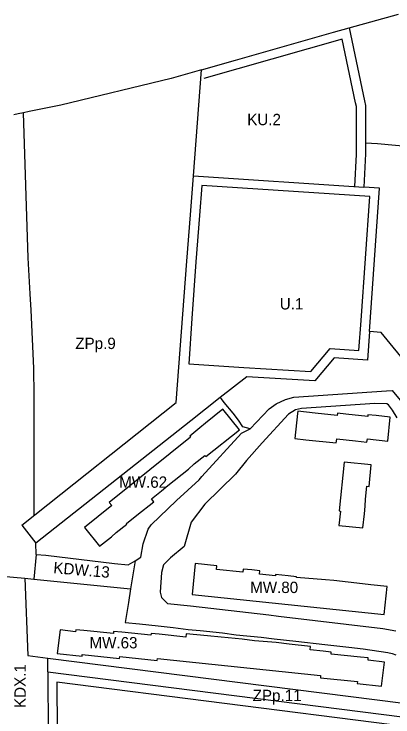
# Model space of a CAD drawing. Extents: x 7424434 to 7425898, y 5541432 to 5542659.
# Drawn here: x 7425417.1 to 7425584.1, y 5542027 to 5542336.8 of the extents above; entities that cross this region are included whole.
import ezdxf

# ---------------------------------------------------------------- set-up
doc = ezdxf.new("R2010")
doc.units = 0
for name, color, linetype in [('linie rozgraniczające', 7, 'Continuous'), ('nieprzekraczalne linie zabudowy', 7, 'Continuous'), ('obowiazujace linie zabudowy', 7, 'Continuous'), ('przeznaczenia terenów', 7, 'Continuous')]:
    doc.layers.add(name, color=color, linetype=linetype)

msp = doc.modelspace()

# ---------------------------------------------------------------- linework, layer by layer
at = {"layer": 'linie rozgraniczające'}
for p, q in [((7425564.85, 5542330.75), (7425586.62, 5542336.78)), ((7425558, 5542328.77), (7425564.85, 5542330.75)), ((7425564.85, 5542330.75), (7425571.55, 5542298.49)), ((7425514.68, 5542316.5), (7425558, 5542328.77)), ((7425499.7, 5542312.23), (7425514.68, 5542316.5)), ((7425499.7, 5542312.23), (7425486.38, 5542308.44)), ((7425496.15, 5542265.55), (7425499.7, 5542312.23)), ((7425486.38, 5542308.44), (7425437.7, 5542296.62)), ((7425437.7, 5542296.62), (7425423.76, 5542293.81)), ((7425571.55, 5542298.49), (7425572.02, 5542296.52)), ((7425423.76, 5542293.81), (7425421.28, 5542293.31)), ((7425572.02, 5542296.52), (7425572.05, 5542280.04)), ((7425418.88, 5542292.83), (7425416.94, 5542292.44)), ((7425421.28, 5542293.31), (7425418.88, 5542292.83)), ((7425423.39, 5542229.29), (7425421.28, 5542293.31)), ((7425572.05, 5542280.04), (7425577.28, 5542279.74)), ((7425572.05, 5542280.04), (7425572.08, 5542275.17)), ((7425577.28, 5542279.74), (7425593.66, 5542278.16)), ((7425572.08, 5542275.17), (7425571.31, 5542260.5)), ((7425494.84, 5542248.31), (7425496.15, 5542265.55)), ((7425496.15, 5542265.55), (7425571.31, 5542260.5)), ((7425578.15, 5542260.04), (7425571.31, 5542260.5)), ((7425573.76, 5542196.85), (7425578.15, 5542260.04)), ((7425493.28, 5542227.87), (7425494.84, 5542248.31)), ((7425424.22, 5542213.47), (7425423.39, 5542229.29)), ((7425488.55, 5542165.65), (7425493.28, 5542227.87)), ((7425424.6, 5542206.27), (7425424.22, 5542213.47)), ((7425425.89, 5542180.72), (7425424.6, 5542206.27)), ((7425573.76, 5542196.85), (7425572.88, 5542184.19)), ((7425578.96, 5542196.49), (7425573.76, 5542196.85)), ((7425613.28, 5542154.25), (7425578.96, 5542196.49)), ((7425558.18, 5542185.23), (7425549.74, 5542175.09)), ((7425572.88, 5542184.19), (7425558.18, 5542185.23)), ((7425425.97, 5542168.7), (7425425.89, 5542180.72)), ((7425519.67, 5542176.97), (7425508, 5542167.76)), ((7425549.74, 5542175.09), (7425519.67, 5542176.97)), ((7425540.42, 5542167.89), (7425581.26, 5542170.76)), ((7425581.26, 5542170.76), (7425583.73, 5542170.93)), ((7425583.73, 5542170.93), (7425600.13, 5542150.9)), ((7425425.97, 5542154.26), (7425425.97, 5542168.7)), ((7425508, 5542167.76), (7425494.99, 5542157.49)), ((7425508.36, 5542167.31), (7425508, 5542167.76)), ((7425509.4, 5542166.07), (7425508.36, 5542167.31)), ((7425532.64, 5542164.96), (7425536.8, 5542166.94)), ((7425536.8, 5542166.94), (7425540.42, 5542167.89)), ((7425420.52, 5542111.53), (7425488.55, 5542165.65)), ((7425509.69, 5542165.65), (7425509.4, 5542166.07)), ((7425513.64, 5542160.82), (7425509.69, 5542165.65)), ((7425529.54, 5542162.73), (7425532.64, 5542164.96)), ((7425576.13, 5542165.08), (7425543.76, 5542163)), ((7425581.46, 5542165.01), (7425576.13, 5542165.08)), ((7425582.21, 5542164.58), (7425581.46, 5542165.01)), ((7425583.91, 5542162.26), (7425582.21, 5542164.58)), ((7425516.08, 5542157.75), (7425513.64, 5542160.82)), ((7425521.15, 5542154), (7425529.54, 5542162.73)), ((7425538.14, 5542160.42), (7425526.47, 5542147.77)), ((7425541.12, 5542162.29), (7425538.14, 5542160.42)), ((7425543.76, 5542163), (7425541.12, 5542162.29)), ((7425586, 5542158.81), (7425583.91, 5542162.26)), ((7425494.99, 5542157.49), (7425426.75, 5542103.63)), ((7425518, 5542154.84), (7425516.08, 5542157.75)), ((7425425.95, 5542115.85), (7425425.97, 5542154.26)), ((7425521.15, 5542154), (7425518, 5542154.84)), ((7425499.92, 5542133.01), (7425517.38, 5542152.01)), ((7425517.38, 5542152.01), (7425521.15, 5542154)), ((7425526.47, 5542147.77), (7425519.51, 5542139.99)), ((7425519.51, 5542139.99), (7425514.77, 5542133.95)), ((7425498.72, 5542131.46), (7425499.92, 5542133.01)), ((7425514.77, 5542133.95), (7425501.25, 5542120.85)), ((7425488.73, 5542122.34), (7425498.72, 5542131.46)), ((7425477.48, 5542111.71), (7425488.73, 5542122.34)), ((7425501.25, 5542120.85), (7425495.17, 5542112.88)), ((7425420.52, 5542111.53), (7425426.75, 5542103.63)), ((7425476.27, 5542109.7), (7425477.48, 5542111.71)), ((7425495.17, 5542112.88), (7425492.04, 5542102.11)), ((7425474.09, 5542103.26), (7425476.27, 5542109.7)), ((7425426.91, 5542098.62), (7425426.75, 5542103.63)), ((7425472.94, 5542097.47), (7425474.09, 5542103.26)), ((7425492.04, 5542102.11), (7425486.11, 5542097.16)), ((7425426.91, 5542098.62), (7425431.09, 5542098.23)), ((7425431.09, 5542098.23), (7425461.44, 5542094.66)), ((7425467.35, 5542094.11), (7425470.54, 5542095.79)), ((7425470.54, 5542095.79), (7425468.51, 5542083.52)), ((7425470.54, 5542095.79), (7425472.94, 5542097.47)), ((7425486.11, 5542097.16), (7425482.92, 5542094.08)), ((7425461.44, 5542094.66), (7425467.35, 5542094.11)), ((7425482.92, 5542094.08), (7425482.12, 5542090.67)), ((7425411.87, 5542089.11), (7425421.8, 5542088.13)), ((7425482.12, 5542090.67), (7425481.47, 5542081.93)), ((7425421.8, 5542088.13), (7425423.13, 5542054.1)), ((7425421.8, 5542088.13), (7425425.88, 5542087.73)), ((7425425.88, 5542087.73), (7425468.51, 5542083.52)), ((7425468.51, 5542083.52), (7425467.51, 5542077.46)), ((7425481.47, 5542081.93), (7425482.16, 5542079.65)), ((7425467.51, 5542077.46), (7425466.06, 5542068.69)), ((7425482.16, 5542079.65), (7425484.82, 5542077.05)), ((7425484.82, 5542077.05), (7425494.84, 5542075.98)), ((7425494.84, 5542075.98), (7425529.41, 5542072.03)), ((7425529.41, 5542072.03), (7425533.72, 5542071.41)), ((7425533.72, 5542071.41), (7425579.75, 5542065.95)), ((7425466.06, 5542068.69), (7425472.4, 5542068.03)), ((7425472.4, 5542068.03), (7425480.57, 5542067.16)), ((7425480.57, 5542067.16), (7425487.18, 5542066.37)), ((7425487.18, 5542066.37), (7425493.91, 5542065.55)), ((7425493.91, 5542065.55), (7425499.19, 5542065.15)), ((7425499.19, 5542065.15), (7425509.05, 5542064.13)), ((7425579.75, 5542065.95), (7425585.36, 5542064.96)), ((7425509.05, 5542064.13), (7425514.98, 5542063.26)), ((7425514.98, 5542063.26), (7425526.1, 5542062.16)), ((7425526.1, 5542062.16), (7425531.78, 5542061.44)), ((7425531.78, 5542061.44), (7425541.28, 5542060.42)), ((7425541.28, 5542060.42), (7425554.15, 5542058.95)), ((7425554.15, 5542058.95), (7425564.69, 5542057.72)), ((7425564.69, 5542057.72), (7425571.01, 5542056.99)), ((7425571.01, 5542056.99), (7425581.82, 5542055.35)), ((7425581.82, 5542055.35), (7425583.8, 5542054.97)), ((7425583.8, 5542054.97), (7425585.45, 5542054.36)), ((7425423.13, 5542054.1), (7425431.98, 5542052.97)), ((7425431.98, 5542052.97), (7425588.81, 5542033.02)), ((7425432, 5542046.92), (7425431.98, 5542052.97)), ((7425432, 5542046.92), (7425588.17, 5542027.05)), ((7425432, 5542046.92), (7425432.08, 5542018.07))]:
    msp.add_line(p, q, dxfattribs=at)
msp.add_lwpolyline([(7425426.91, 5542098.62), (7425426.91, 5542098.62), (7425425.88, 5542087.73)], dxfattribs=at)
at = {"layer": 'nieprzekraczalne linie zabudowy'}
msp.add_lwpolyline([(7425567.32, 5542260.71), (7425568.06, 5542274.85), (7425568.02, 5542296.05), (7425567.65, 5542297.62), (7425561.81, 5542325.69), (7425515.77, 5542312.65), (7425500.8, 5542308.38)], dxfattribs=at)
for points in [[(7425495.5, 5542202.58), (7425494.09, 5542182.58), (7425518.39, 5542181.06), (7425547.96, 5542179.21), (7425556.42, 5542189.36), (7425569.17, 5542188.46), (7425570.08, 5542201.66), (7425573.88, 5542256.32), (7425499.84, 5542261.29), (7425498.83, 5542248.01), (7425497.27, 5542227.57)], [(7425581.48, 5542002.23), (7425583.77, 5542023.58), (7425436.01, 5542042.38), (7425435.98, 5542041.67), (7425436.07, 5542021.58), (7425536, 5542008.58), (7425544.77, 5542007.43)]]:
    msp.add_lwpolyline(points, close=True, dxfattribs=at)
at = {"layer": 'obowiazujace linie zabudowy'}
for points in [[(7425448.17, 5542110.52), (7425454.81, 5542102.21), (7425460.05, 5542106.39), (7425462.19, 5542108.27), (7425466.87, 5542112.01), (7425466.69, 5542112.23), (7425471.28, 5542115.89), (7425478.75, 5542121.85), (7425477.67, 5542123.2), (7425482.06, 5542126.71), (7425484.92, 5542129), (7425493.97, 5542136.24), (7425496.45, 5542138.5), (7425501.2, 5542142.29), (7425501.64, 5542141.73), (7425516.5, 5542153.6), (7425509.18, 5542162.71), (7425501.51, 5542156.55), (7425499.06, 5542154.39), (7425494.53, 5542150.76), (7425494.87, 5542150.33), (7425459.03, 5542121.54), (7425460.15, 5542120.14)], [(7425542.05, 5542160.79), (7425540.88, 5542149.71), (7425545.71, 5542149.2), (7425559.14, 5542147.78), (7425559.23, 5542148.61), (7425559.35, 5542149.63), (7425567.57, 5542148.71), (7425572.69, 5542148.14), (7425572.86, 5542149.62), (7425581.84, 5542148.61), (7425582.9, 5542159.19), (7425576.71, 5542159.79), (7425573.08, 5542160.14), (7425573.01, 5542159.45), (7425563.31, 5542160.45), (7425559.67, 5542160.82), (7425559.57, 5542159.82), (7425549.84, 5542160.93), (7425542.16, 5542161.81)], [(7425562.57, 5542139.31), (7425560.46, 5542117.79), (7425560.95, 5542117.73), (7425560.27, 5542111.39), (7425570.93, 5542110.33), (7425571.54, 5542116.46), (7425571.83, 5542119.93), (7425572.1, 5542122.97), (7425572.59, 5542128.67), (7425573.61, 5542128.58), (7425574.6, 5542138.06)], [(7425496.96, 5542094.58), (7425495.57, 5542080.93), (7425580.32, 5542072.2), (7425581.59, 5542084.51), (7425574.46, 5542085.25), (7425570.78, 5542085.63), (7425558.05, 5542087.08), (7425554.42, 5542087.5), (7425541.65, 5542088.49), (7425541.65, 5542088.49), (7425541.68, 5542088.81), (7425537.99, 5542089.21), (7425532.38, 5542089.82), (7425532.32, 5542089.22), (7425525.25, 5542089.99), (7425525.41, 5542091.46), (7425521.87, 5542091.78), (7425518.1, 5542092.12), (7425517.99, 5542090.82), (7425506.32, 5542092), (7425506.48, 5542093.63)], [(7425436.13, 5542054.9), (7425447.06, 5542053.74), (7425447.15, 5542054.58), (7425463.59, 5542052.82), (7425463.67, 5542053.59), (7425480.26, 5542051.83), (7425480.36, 5542052.79), (7425552.24, 5542045.26), (7425552.14, 5542044.26), (7425568.52, 5542042.55), (7425568.43, 5542041.7), (7425579.05, 5542040.59), (7425580.38, 5542051.14), (7425573.15, 5542052.06), (7425573.27, 5542053.04), (7425569.89, 5542053.38), (7425556.83, 5542054.68), (7425556.92, 5542055.62), (7425553.44, 5542055.96), (7425547.58, 5542056.54), (7425547.73, 5542058.08), (7425538.4, 5542059.02), (7425532.64, 5542059.78), (7425523.11, 5542060.6), (7425517.68, 5542061.3), (7425508.34, 5542062.1), (7425502.43, 5542062.76), (7425492.98, 5542063.67), (7425492.84, 5542062.19), (7425481.01, 5542063.43), (7425477.48, 5542063.8), (7425477.39, 5542062.97), (7425464.66, 5542064.31), (7425460.96, 5542064.7), (7425460.87, 5542063.84), (7425447.89, 5542065.04), (7425444.32, 5542065.37), (7425444.24, 5542064.5), (7425437.38, 5542065.33)]]:
    msp.add_lwpolyline(points, close=True, dxfattribs=at)

# ---------------------------------------------------------------- texts
at = {"layer": 'przeznaczenia terenów'}
for s, p in [('KU.2', (7425519.89, 5542287.81)), ('U.1', (7425534.25, 5542206.58)), ('ZPp.9', (7425444.11, 5542189.15)), ('MW.62', (7425463.42, 5542128)), ('MW.80', (7425521.18, 5542081.61)), ('MW.63', (7425450.35, 5542057.22)), ('ZPp.11', (7425522.3, 5542033.97))]:
    msp.add_text(s, height=5, dxfattribs=at).set_placement(p)
for s, rotation, p in [('KDW.13', 355.1061, (7425434.27, 5542090.38)), ('KDX.1', 90, (7425422.26, 5542030.93))]:
    msp.add_text(s, height=5, rotation=rotation, dxfattribs=at).set_placement(p)

doc.saveas('drawing.dxf')
